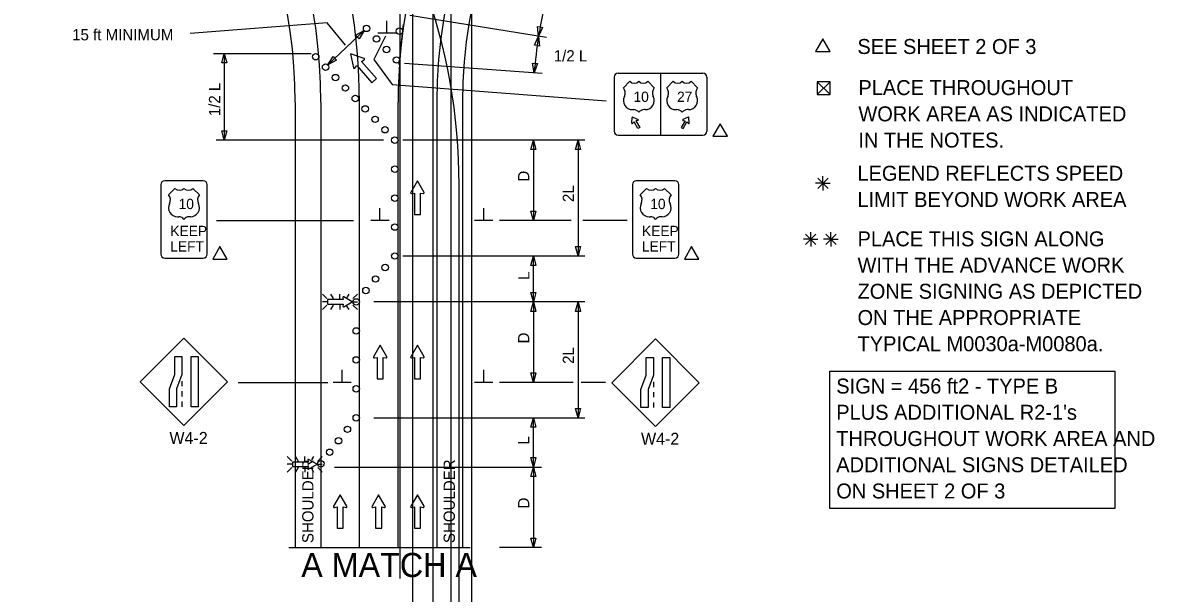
# Model space of a CAD drawing. Extents: x 16554 to 19508, y 5694 to 7079.
# Drawn here: x 16738 to 17442, y 6130 to 6485 of the extents above; entities that cross this region are included whole.
import ezdxf

# ---------------------------------------------------------------- set-up
doc = ezdxf.new("R2010")
doc.units = 0
for name, color, linetype in [('ALI_LEGAL_EX', 7, 'Continuous'), ('MT_SCRATCH_LEVEL_E', 7, 'Continuous'), ('PAVT_EDGE_EX', 7, 'Continuous'), ('TRAFFIC_SIGNS_PR', 7, 'Continuous'), ('TYPICAL_EX', 7, 'Continuous'), ('TYPICAL_TEXT_DIMEN_EX', 7, 'Continuous'), ('TYPICAL_TEXT_DIMEN_PR', 7, 'Continuous')]:
    doc.layers.add(name, color=color, linetype=linetype)

msp = doc.modelspace()

# ---------------------------------------------------------------- linework, layer by layer
at = {"layer": 'ALI_LEGAL_EX'}
for p, q in [((16980.68, 6974.12), (16980.68, 6155.98)), ((17004.68, 6974.12), (17004.68, 6155.98)), ((16980.68, 6877.04), (16980.68, 6013.12)), ((17004.68, 6877.04), (17004.68, 6013.12)), ((16973.01, 6139.03), (16973.01, 6639.38)), ((16993.65, 6024.8), (16993.65, 6525.15)), ((17017.65, 6024.8), (17017.65, 6525.15)), ((16947.82, 6158.38), (16947.82, 6435.06)), ((16971.82, 6158.38), (16971.82, 6435.06)), ((17009.75, 5773.57), (17009.75, 6383.76))]:
    msp.add_line(p, q, dxfattribs=at)
for points in [[(16972.59, 6458.6), (16975.21, 6483.46)], [(16947.82, 6358.38), (16947.82, 6383.38)], [(16971.82, 6358.38), (16971.82, 6383.38)], [(16947.82, 6258.38), (16947.82, 6283.38)], [(16971.82, 6258.38), (16971.82, 6283.38)], [(16947.82, 6158.38), (16947.82, 6183.38)], [(16971.82, 6158.38), (16971.82, 6183.38)]]:
    msp.add_lwpolyline(points, dxfattribs=at)
for centre, radius, start, end in [((16583.82, 6435.06), 364, 0, 40.19088), ((17311.82, 6435.06), 340, 137.51599, 180), ((16645.75, 6383.76), 364, 0, 40.19088)]:
    msp.add_arc(centre, radius, start, end, dxfattribs=at)
at = {"layer": 'MT_SCRATCH_LEVEL_E'}
for p, q in [((16983.79, 6386.25), (16979.68, 6379.01)), ((16987.94, 6379.01), (16983.79, 6386.25)), ((16980.16, 6378.32), (16981.94, 6378.64)), ((16981.94, 6378.64), (16981.94, 6365.38)), ((16985.68, 6365.38), (16985.68, 6378.64)), ((16985.68, 6378.64), (16987.46, 6378.32)), ((16981.94, 6365.38), (16985.68, 6365.38)), ((16960.72, 6284.09), (16956.61, 6276.85)), ((16964.86, 6276.85), (16960.72, 6284.09)), ((16983.79, 6284.09), (16979.68, 6276.85)), ((16987.94, 6276.85), (16983.79, 6284.09)), ((16957.09, 6276.17), (16958.87, 6276.48)), ((16958.87, 6276.48), (16958.87, 6263.23)), ((16962.61, 6263.23), (16962.61, 6276.48)), ((16962.61, 6276.48), (16964.39, 6276.17)), ((16980.16, 6276.17), (16981.94, 6276.48)), ((16981.94, 6276.48), (16981.94, 6263.23)), ((16985.68, 6263.23), (16985.68, 6276.48)), ((16985.68, 6276.48), (16987.46, 6276.17)), ((16958.87, 6263.23), (16962.61, 6263.23)), ((16981.94, 6263.23), (16985.68, 6263.23)), ((16935.83, 6191.19), (16931.72, 6183.95)), ((16939.98, 6183.95), (16935.83, 6191.19)), ((16959.74, 6191.19), (16955.62, 6183.95)), ((16963.88, 6183.95), (16959.74, 6191.19)), ((16983.79, 6191.19), (16979.68, 6183.95)), ((16987.94, 6183.95), (16983.79, 6191.19)), ((16932.2, 6183.27), (16933.98, 6183.58)), ((16933.98, 6183.58), (16933.98, 6170.32)), ((16937.72, 6170.32), (16937.72, 6183.58)), ((16937.72, 6183.58), (16939.5, 6183.27)), ((16956.11, 6183.27), (16957.88, 6183.58)), ((16957.88, 6183.58), (16957.88, 6170.32)), ((16961.63, 6170.32), (16961.63, 6183.58)), ((16961.63, 6183.58), (16963.4, 6183.27)), ((16980.16, 6183.27), (16981.94, 6183.58)), ((16981.94, 6183.58), (16981.94, 6170.32)), ((16985.68, 6170.32), (16985.68, 6183.58)), ((16985.68, 6183.58), (16987.46, 6183.27)), ((16933.98, 6170.32), (16937.72, 6170.32)), ((16957.88, 6170.32), (16961.63, 6170.32)), ((16981.94, 6170.32), (16985.68, 6170.32))]:
    msp.add_line(p, q, dxfattribs=at)
for centre, start, end in [((16980.09, 6378.78), 150.42484, 279.96381), ((16987.53, 6378.78), 260.03619, 29.77312), ((16957.01, 6276.63), 150.42484, 279.96381), ((16964.46, 6276.63), 260.03619, 29.77312), ((16980.09, 6276.63), 150.42484, 279.96381), ((16987.53, 6276.63), 260.03619, 29.77312), ((16932.13, 6183.72), 150.42484, 279.96381), ((16939.57, 6183.73), 260.03619, 29.77312), ((16956.03, 6183.72), 150.42484, 279.96381), ((16963.47, 6183.73), 260.03619, 29.77312), ((16980.09, 6183.72), 150.42484, 279.96381), ((16987.53, 6183.73), 260.03619, 29.77312)]:
    msp.add_arc(centre, 0.463, start, end, dxfattribs=at)
at = {"layer": 'PAVT_EDGE_EX'}
for p, q in [((16907.82, 6435.06), (16907.82, 6158.38)), ((16923.82, 6435.06), (16923.82, 6158.38)), ((16995.82, 6435.06), (16995.82, 6158.38)), ((17011.82, 6435.06), (17011.82, 6158.38))]:
    msp.add_line(p, q, dxfattribs=at)
for centre, radius, start, end in [((17311.82, 6435.06), 316, 105.2177, 180), ((16583.82, 6435.06), 340, 0, 61.48623), ((17311.82, 6435.06), 300, 105.2177, 180), ((16583.82, 6435.06), 324, 0, 61.48623), ((17311.82, 6435.06), 300, 180, 180.00000277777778)]:
    msp.add_arc(centre, radius, start, end, dxfattribs=at)
at = {"layer": 'TRAFFIC_SIGNS_PR'}
for p, q in [((17106.11, 6450.65), (17106.11, 6417.05)), ((17108.51, 6453.05), (17161.31, 6453.05)), ((17134.91, 6453.05), (17134.91, 6414.65)), ((17163.71, 6450.65), (17163.71, 6417.05)), ((17117.09, 6422), (17117.37, 6425.62)), ((17117.74, 6425.84), (17121.02, 6424.27)), ((17152.07, 6425.84), (17148.8, 6424.27)), ((17152.73, 6422), (17152.44, 6425.62)), ((17108.51, 6414.65), (17161.31, 6414.65)), ((16824.36, 6383.86), (16824.36, 6340.66)), ((16850.76, 6386.26), (16826.76, 6386.26)), ((16853.16, 6340.66), (16853.16, 6383.86)), ((17117.49, 6383.86), (17117.49, 6340.66)), ((17143.88, 6386.26), (17119.88, 6386.26)), ((17146.28, 6340.66), (17146.28, 6383.86)), ((16826.76, 6338.26), (16850.76, 6338.26)), ((17119.88, 6338.26), (17143.88, 6338.26)), ((16927.59, 6313.05), (16924.77, 6315.87)), ((16927.59, 6311.02), (16924.77, 6311.02)), ((16929.89, 6315.87), (16931.52, 6313.05)), ((16935.68, 6313.05), (16935.68, 6315.87)), ((16941.15, 6315.87), (16939.94, 6313.77)), ((16946.58, 6315.86), (16943.76, 6313.05)), ((16943.76, 6311.02), (16946.58, 6311.02)), ((16927.59, 6308.98), (16924.77, 6306.16)), ((16931.54, 6308.98), (16929.91, 6306.16)), ((16935.68, 6308.98), (16935.68, 6306.16)), ((16939.86, 6308.35), (16941.12, 6306.16)), ((16946.58, 6306.16), (16943.76, 6308.98)), ((16838.75, 6288.47), (16811.6, 6261.32)), ((16865.9, 6261.32), (16838.75, 6288.47)), ((17131.83, 6287.95), (17104.68, 6260.79)), ((17158.99, 6260.79), (17131.83, 6287.95)), ((16811.6, 6261.32), (16838.75, 6234.17)), ((16837.5, 6261.81), (16837.5, 6258.61)), ((16838.75, 6234.17), (16865.9, 6261.32)), ((17104.68, 6260.79), (17131.83, 6233.64)), ((17130.59, 6261.28), (17130.59, 6258.08)), ((17131.83, 6233.64), (17158.99, 6260.79)), ((16837.5, 6255.41), (16837.5, 6252.21)), ((17130.59, 6254.88), (17130.59, 6251.68)), ((16837.5, 6249.01), (16837.5, 6245.81)), ((17130.59, 6248.48), (17130.59, 6245.28)), ((16905.72, 6212.1), (16902.9, 6214.92)), ((16908.01, 6214.91), (16909.64, 6212.1)), ((16913.8, 6212.1), (16913.8, 6214.91)), ((16919.27, 6214.91), (16918.06, 6212.82)), ((16924.71, 6214.91), (16921.89, 6212.1)), ((16905.72, 6210.06), (16902.9, 6210.06)), ((16905.72, 6208.03), (16902.9, 6205.21)), ((16909.67, 6208.03), (16908.04, 6205.21)), ((16913.8, 6208.03), (16913.8, 6205.21)), ((16917.99, 6207.4), (16919.25, 6205.21)), ((16921.89, 6210.06), (16924.71, 6210.06)), ((16924.71, 6205.21), (16921.89, 6208.03))]:
    msp.add_line(p, q, dxfattribs=at)
for points in [[(17120.98, 6423.79), (17119.57, 6423.4), (17122.08, 6419.42), (17120.76, 6418.65), (17118.57, 6422.82), (17117.53, 6421.79)], [(17148.83, 6423.79), (17150.24, 6423.4), (17147.73, 6419.42), (17149.06, 6418.65), (17151.25, 6422.82), (17152.29, 6421.79)], [(16937.5, 6313.7), (16937.73, 6312.4), (16928.01, 6312.4), (16928.01, 6309.66), (16937.73, 6309.66), (16937.5, 6308.35)], [(16938, 6308), (16943.31, 6311.02), (16938, 6314.06)], [(16915.63, 6212.74), (16915.86, 6211.45), (16906.14, 6211.45), (16906.14, 6208.7), (16915.86, 6208.7), (16915.63, 6207.4)], [(16916.13, 6207.05), (16921.44, 6210.06), (16916.13, 6213.1)]]:
    msp.add_lwpolyline(points, dxfattribs=at)
for points in [[(16837.5, 6277.06), (16837.5, 6265.88), (16834.16, 6256.99), (16834.16, 6245.81), (16829.66, 6245.81), (16829.66, 6256.99), (16833.01, 6265.88), (16833.01, 6277.06)], [(16847.64, 6277.06), (16847.64, 6245.81), (16843.14, 6245.81), (16843.14, 6277.06)], [(17130.59, 6276.53), (17130.59, 6265.35), (17127.24, 6256.47), (17127.24, 6245.28), (17122.75, 6245.28), (17122.75, 6256.47), (17126.09, 6265.35), (17126.09, 6276.53)], [(17140.72, 6276.53), (17140.72, 6245.28), (17136.23, 6245.28), (17136.23, 6276.53)]]:
    msp.add_lwpolyline(points, close=True, dxfattribs=at)
for centre in [(16952.24, 6480.91), (16972.68, 6479.22), (16958.43, 6474.38), (16920.63, 6463.35), (16964.62, 6467.85), (16926.78, 6456.87), (16970.82, 6461.32), (16932.93, 6450.38), (16939.07, 6443.89), (16945.22, 6437.4), (16951.37, 6430.92), (16957.52, 6424.43), (16963.67, 6417.94), (16969.82, 6411.46), (16969.82, 6411.46), (16969.82, 6393.46), (16969.82, 6375.46), (16969.82, 6357.46), (16969.82, 6339.51), (16963.82, 6332.37), (16957.82, 6325.23), (16951.82, 6318.09), (16945.82, 6310.95), (16945.82, 6292.94), (16945.82, 6274.94), (16945.82, 6256.94), (16945.82, 6238.94), (16940.32, 6231.81), (16934.82, 6224.69), (16929.32, 6217.56), (16923.83, 6210.43)]:
    msp.add_circle(centre, 2, dxfattribs=at)
for centre, radius, start, end in [((17108.51, 6450.65), 2.4, 90, 180), ((17108.51, 6450.65), 2.4, 90, 180), ((17161.31, 6450.65), 2.4, 0, 90), ((17117.35, 6421.98), 0.26, 175.51775, 314.01151), ((17117.63, 6425.6), 0.26, 64.48226, 175.51774), ((17120.91, 6424.04), 0.26, 285.9885, 64.48226), ((17148.91, 6424.04), 0.26, 115.51774, 254.0115), ((17152.19, 6425.6), 0.26, 4.48226, 115.51774), ((17152.47, 6421.98), 0.26, 225.98849, 4.48225), ((17108.51, 6417.05), 2.4, 180, 270), ((17161.31, 6417.05), 2.4, 270, 0), ((16826.76, 6383.86), 2.4, 90, 180), ((16850.76, 6383.86), 2.4, 0, 90), ((17119.88, 6383.86), 2.4, 90, 180), ((17143.88, 6383.86), 2.4, 0, 90), ((16826.76, 6340.66), 2.4, 180, 270), ((16850.76, 6340.66), 2.4, 270, 0), ((17119.88, 6340.66), 2.4, 180, 270), ((17143.88, 6340.66), 2.4, 270, 0), ((16937.84, 6313.76), 0.341, 61.48329, 189.95933), ((16937.84, 6308.3), 0.341, 170.73078, 298.89165), ((16915.97, 6212.8), 0.341, 61.48329, 189.95933), ((16915.97, 6207.35), 0.341, 170.73078, 298.89165)]:
    msp.add_arc(centre, radius, start, end, dxfattribs=at)
at = {"layer": 'TYPICAL_EX'}
for p, q in [((17111.86, 6444.05), (17115.86, 6448.05)), ((17131.06, 6444.05), (17127.06, 6448.05)), ((17138.76, 6444.05), (17142.76, 6448.05)), ((17157.96, 6444.05), (17153.96, 6448.05)), ((17117.45, 6430.44), (17118.25, 6430.44)), ((17125.46, 6430.44), (17124.66, 6430.44)), ((17144.35, 6430.44), (17145.15, 6430.44)), ((17152.36, 6430.44), (17151.56, 6430.44)), ((16829.16, 6377.46), (16833.16, 6381.46)), ((16848.36, 6377.46), (16844.36, 6381.46)), ((17122.28, 6377.46), (17126.28, 6381.46)), ((17141.49, 6377.46), (17137.49, 6381.46)), ((16834.75, 6363.85), (16835.55, 6363.85)), ((16842.76, 6363.85), (16841.96, 6363.85)), ((17127.88, 6363.85), (17128.68, 6363.85)), ((17135.89, 6363.85), (17135.09, 6363.85))]:
    msp.add_line(p, q, dxfattribs=at)
for centre, radius, start, end in [((17108.07, 6440.85), 4.96, 333.09768, 40.19361), ((17118.66, 6450.96), 4.04, 226.14041, 313.85958), ((17124.26, 6450.96), 4.04, 226.14042, 313.85959), ((17134.85, 6440.85), 4.96, 139.80639, 206.90233), ((17134.97, 6440.85), 4.96, 333.09768, 40.19361), ((17145.56, 6450.96), 4.04, 226.14041, 313.85958), ((17151.16, 6450.96), 4.04, 226.14042, 313.85959), ((17161.75, 6440.85), 4.96, 139.80639, 206.90233), ((17117.46, 6436.03), 5.59, 152.6698, 269.90132), ((17125.45, 6436.03), 5.59, 270.09868, 27.3302), ((17144.36, 6436.03), 5.59, 152.6698, 269.90132), ((17152.35, 6436.03), 5.59, 270.09868, 27.3302), ((17118.26, 6426.43), 4.01, 37.1038, 90.13853), ((17124.65, 6426.43), 4.01, 89.86147, 142.8962), ((17145.16, 6426.43), 4.01, 37.1038, 90.13853), ((17151.55, 6426.43), 4.01, 89.86147, 142.8962), ((16835.96, 6384.37), 4.04, 226.14041, 313.85958), ((16841.56, 6384.37), 4.04, 226.14042, 313.85959), ((17129.09, 6384.37), 4.04, 226.14041, 313.85958), ((17134.69, 6384.37), 4.04, 226.14042, 313.85959), ((16825.37, 6374.26), 4.96, 333.09768, 40.19361), ((16852.15, 6374.26), 4.96, 139.80639, 206.90233), ((17118.49, 6374.26), 4.96, 333.09768, 40.19361), ((17145.28, 6374.26), 4.96, 139.80639, 206.90233), ((16834.76, 6369.44), 5.59, 152.6698, 269.90132), ((16842.75, 6369.44), 5.59, 270.09868, 27.3302), ((17127.89, 6369.44), 5.59, 152.6698, 269.90132), ((17135.88, 6369.44), 5.59, 270.09868, 27.3302), ((16835.56, 6359.84), 4.01, 37.1038, 90.13853), ((16841.95, 6359.84), 4.01, 89.86147, 142.8962), ((17128.69, 6359.84), 4.01, 37.1038, 90.13853), ((17135.08, 6359.84), 4.01, 89.86147, 142.8962)]:
    msp.add_arc(centre, radius, start, end, dxfattribs=at)
at = {"layer": 'TYPICAL_TEXT_DIMEN_EX'}
msp.add_lwpolyline([(17240.08, 6267.86), (17417.36, 6267.86), (17417.36, 6182.54), (17240.08, 6182.54)], close=True, dxfattribs=at)
at = {"layer": 'TYPICAL_TEXT_DIMEN_PR'}
for p, q in [((16964.92, 6477.95), (16964.92, 6485.73)), ((17064.05, 6475.22), (16979.21, 6488.97)), ((16927.8, 6484.32), (16842.59, 6477.76)), ((16939.16, 6470.62), (16927.8, 6484.32)), ((16950.78, 6479.54), (16928.23, 6458.24)), ((16945.44, 6476.66), (16950.78, 6479.54)), ((16950.78, 6479.54), (16947.6, 6474.37)), ((16970.55, 6477.95), (16959.3, 6477.95)), ((17059.11, 6476.02), (17058.5, 6482.06)), ((17058.5, 6482.06), (17060.05, 6481.81)), ((17059.11, 6476.02), (17058.5, 6482.06)), ((17058.5, 6482.06), (17060.05, 6481.81)), ((17061.6, 6481.55), (17059.11, 6476.02)), ((17061.6, 6481.55), (17059.11, 6476.02)), ((17060.05, 6481.81), (17061.6, 6481.55)), ((17060.05, 6481.81), (17061.6, 6481.55)), ((16946.52, 6475.52), (16945.44, 6476.66)), ((16947.6, 6474.37), (16946.52, 6475.52)), ((16964.04, 6476.17), (16956.66, 6461.67)), ((17056.63, 6470.48), (17059.11, 6476.02)), ((17059.11, 6476.02), (17059.73, 6469.98)), ((16857.14, 6465.35), (16917.72, 6465.35)), ((16862.25, 6459.49), (16863.82, 6465.35)), ((16863.82, 6465.35), (16863.82, 6411.51)), ((16863.82, 6465.35), (16865.39, 6459.49)), ((16950.7, 6462.31), (16942.28, 6465.2)), ((16942.28, 6465.2), (16944.08, 6456.51)), ((17058.18, 6470.23), (17056.63, 6470.48)), ((17059.73, 6469.98), (17058.18, 6470.23)), ((16863.82, 6459.49), (16862.25, 6459.49)), ((16865.39, 6459.49), (16863.82, 6459.49)), ((16928.23, 6458.24), (16931.41, 6463.41)), ((16933.57, 6461.12), (16928.23, 6458.24)), ((16931.41, 6463.41), (16932.49, 6462.26)), ((16932.49, 6462.26), (16933.57, 6461.12)), ((16944.95, 6456.3), (16946.15, 6457.8)), ((16946.15, 6457.8), (16955.47, 6447.16)), ((16949.15, 6460.43), (16950.8, 6461.43)), ((16958.47, 6449.8), (16949.15, 6460.43)), ((16956.66, 6461.67), (16968.23, 6446.16)), ((17061.46, 6452.97), (16975.72, 6459.1)), ((17056.47, 6453.32), (17055.32, 6459.28)), ((17055.32, 6459.28), (17056.89, 6459.17)), ((17058.45, 6459.06), (17056.47, 6453.32)), ((17056.89, 6459.17), (17058.45, 6459.06)), ((16955.47, 6447.16), (16958.47, 6449.8)), ((16968.23, 6446.16), (17101.17, 6435.93)), ((17232.27, 6447.79), (17240.27, 6439.79)), ((17232.27, 6439.79), (17240.27, 6447.79)), ((16863.82, 6411.51), (16862.25, 6417.37)), ((16862.25, 6417.37), (16863.82, 6417.37)), ((16863.82, 6417.37), (16865.39, 6417.37)), ((16865.39, 6417.37), (16863.82, 6411.51)), ((16962.71, 6411.51), (16858.82, 6411.51)), ((17087.96, 6411.51), (16974.86, 6411.51)), ((17054.34, 6405.65), (17055.91, 6411.51)), ((17055.91, 6411.51), (17057.48, 6405.65)), ((17055.91, 6411.51), (17055.91, 6361.51)), ((17082.15, 6405.65), (17083.72, 6411.51)), ((17083.72, 6411.51), (17083.72, 6339.51)), ((17083.72, 6411.51), (17085.29, 6405.65)), ((17055.91, 6405.65), (17054.34, 6405.65)), ((17057.48, 6405.65), (17055.91, 6405.65)), ((17083.72, 6405.65), (17082.15, 6405.65)), ((17085.29, 6405.65), (17083.72, 6405.65)), ((17232.64, 6387.92), (17239.02, 6381.54)), ((17239.02, 6387.92), (17232.64, 6381.54)), ((17235.83, 6384.73), (17235.83, 6389.18)), ((17235.83, 6384.73), (17231.3, 6384.73)), ((17235.83, 6384.73), (17239.02, 6384.73)), ((17235.83, 6384.73), (17240.31, 6384.73)), ((17235.83, 6384.73), (17235.83, 6380.23)), ((16960.57, 6361.51), (16960.57, 6369.29)), ((17025.04, 6361.51), (17025.04, 6369.29)), ((17055.91, 6361.51), (17054.34, 6367.37)), ((17054.34, 6367.37), (17055.91, 6367.37)), ((17055.91, 6367.37), (17057.48, 6367.37)), ((17057.48, 6367.37), (17055.91, 6361.51)), ((16858.91, 6361.51), (16944.03, 6361.51)), ((16966.19, 6361.51), (16954.94, 6361.51)), ((17030.66, 6361.51), (17019.41, 6361.51)), ((17079.49, 6361.51), (17034.91, 6361.51)), ((17114.15, 6361.51), (17086.72, 6361.51)), ((17225.05, 6353.13), (17231.42, 6346.75)), ((17231.42, 6353.13), (17225.05, 6346.75)), ((17228.24, 6349.94), (17228.24, 6354.4)), ((17237.6, 6353.13), (17243.98, 6346.75)), ((17243.98, 6353.13), (17237.6, 6346.75)), ((17240.79, 6349.94), (17240.79, 6354.4)), ((17083.72, 6339.51), (17082.15, 6345.37)), ((17082.15, 6345.37), (17083.72, 6345.37)), ((17083.72, 6345.37), (17085.29, 6345.37)), ((17085.29, 6345.37), (17083.72, 6339.51)), ((17228.24, 6349.94), (17223.7, 6349.94)), ((17228.24, 6349.94), (17231.42, 6349.94)), ((17228.24, 6349.94), (17232.71, 6349.94)), ((17228.24, 6349.94), (17228.24, 6345.44)), ((17240.79, 6349.94), (17236.26, 6349.94)), ((17240.79, 6349.94), (17243.98, 6349.94)), ((17240.79, 6349.94), (17245.27, 6349.94)), ((17240.79, 6349.94), (17240.79, 6345.44)), ((16974.86, 6339.51), (17087.96, 6339.51)), ((17054.34, 6333.65), (17055.91, 6339.51)), ((17055.91, 6310.94), (17055.91, 6339.51)), ((17055.91, 6339.51), (17057.48, 6333.65)), ((17055.91, 6333.65), (17054.34, 6333.65)), ((17057.48, 6333.65), (17055.91, 6333.65)), ((17055.91, 6310.94), (17054.34, 6316.81)), ((17054.34, 6316.81), (17055.91, 6316.81)), ((17055.91, 6316.81), (17057.48, 6316.81)), ((17057.48, 6316.81), (17055.91, 6310.94)), ((17087.96, 6310.94), (16956.81, 6310.94)), ((17054.34, 6305.08), (17055.91, 6310.94)), ((17055.91, 6310.94), (17055.91, 6260.94)), ((17055.91, 6310.94), (17057.48, 6305.08)), ((17082.15, 6305.08), (17083.72, 6310.94)), ((17083.72, 6310.94), (17085.29, 6305.08)), ((17083.72, 6310.94), (17083.72, 6238.94)), ((17055.91, 6305.08), (17054.34, 6305.08)), ((17057.48, 6305.08), (17055.91, 6305.08)), ((17083.72, 6305.08), (17082.15, 6305.08)), ((17085.29, 6305.08), (17083.72, 6305.08)), ((16937.1, 6260.94), (16937.1, 6268.73)), ((17025.04, 6260.94), (17025.04, 6268.73)), ((16872.52, 6260.94), (16928.11, 6260.94)), ((16942.73, 6260.94), (16931.48, 6260.94)), ((17030.66, 6260.94), (17019.41, 6260.94)), ((17080.65, 6260.94), (17034.91, 6260.94)), ((17055.91, 6260.94), (17054.34, 6266.81)), ((17054.34, 6266.81), (17055.91, 6266.81)), ((17055.91, 6266.81), (17057.48, 6266.81)), ((17057.48, 6266.81), (17055.91, 6260.94)), ((17100.8, 6260.94), (17085.61, 6260.94)), ((16956.81, 6238.94), (17087.96, 6238.94)), ((17054.34, 6233.08), (17055.91, 6238.94)), ((17055.91, 6208.38), (17055.91, 6238.94)), ((17055.91, 6238.94), (17057.48, 6233.08)), ((17083.72, 6238.94), (17082.15, 6244.81)), ((17082.15, 6244.81), (17083.72, 6244.81)), ((17083.72, 6244.81), (17085.29, 6244.81)), ((17085.29, 6244.81), (17083.72, 6238.94)), ((17055.91, 6233.08), (17054.34, 6233.08)), ((17057.48, 6233.08), (17055.91, 6233.08)), ((17055.91, 6208.38), (17054.34, 6214.24)), ((17054.34, 6214.24), (17055.91, 6214.24)), ((17055.91, 6214.24), (17057.48, 6214.24)), ((17057.48, 6214.24), (17055.91, 6208.38)), ((16932.31, 6208.38), (17060.91, 6208.38)), ((16933.08, 6208.38), (17060.91, 6208.38)), ((17054.34, 6202.52), (17055.91, 6208.38)), ((17055.91, 6208.38), (17055.91, 6158.38)), ((17055.91, 6208.38), (17057.48, 6202.52)), ((17055.91, 6202.52), (17054.34, 6202.52)), ((17057.48, 6202.52), (17055.91, 6202.52)), ((17055.91, 6158.38), (17054.34, 6164.24)), ((17054.34, 6164.24), (17055.91, 6164.24)), ((17055.91, 6164.24), (17057.48, 6164.24)), ((17057.48, 6164.24), (17055.91, 6158.38)), ((16903.89, 6158.38), (17016.54, 6158.38)), ((17060.91, 6158.38), (17034.91, 6158.38))]:
    msp.add_line(p, q, dxfattribs=at)
for points in [[(17235.74, 6474.5), (17231.22, 6466.67), (17240.27, 6466.67)], [(17232.27, 6447.79), (17232.27, 6439.79), (17240.27, 6439.79), (17240.27, 6447.79)], [(17171.94, 6421.72), (17167.42, 6413.89), (17176.47, 6413.89)], [(16861.12, 6345.44), (16856.6, 6337.6), (16865.65, 6337.6)], [(17154.26, 6345.44), (17149.73, 6337.6), (17158.78, 6337.6)]]:
    msp.add_lwpolyline(points, close=True, dxfattribs=at)
for centre, radius, start, end in [((17311.82, 6435.06), 256, 167.0592, 170.79286), ((17311.82, 6435.06), 256, 170.79286, 175.90841), ((16950.53, 6461.84), 0.494, 301.27371, 71.01063), ((16944.56, 6456.61), 0.494, 191.66235, 321.20132)]:
    msp.add_arc(centre, radius, start, end, dxfattribs=at)

# ---------------------------------------------------------------- texts
at = {"layer": 'TRAFFIC_SIGNS_PR'}
for s, height, p in [('10', 6.4, (17118.12, 6435.25)), ('27', 6.4, (17145.19, 6435.25)), ('10', 6.4, (16835.42, 6368.66)), ('10', 6.4, (17128.54, 6368.66)), ('KEEP', 6.4, (16830.29, 6351.86)), ('KEEP', 6.4, (17123.42, 6351.86)), ('LEFT', 6.4, (16830.21, 6342.26)), ('LEFT', 6.4, (17123.33, 6342.26)), ('W4-2', 7.44, (16829.71, 6222.73)), ('W4-2', 7.44, (17122.79, 6222.2))]:
    msp.add_text(s, height=height, dxfattribs=at).set_placement(p)
at = {"layer": 'TYPICAL_TEXT_DIMEN_EX'}
for s, p in [('SEE SHEET 2 OF 3', (17257.28, 6465.04)), ('PLACE THROUGHOUT', (17257.89, 6439.49)), ('WORK AREA AS INDICATED', (17257.89, 6423.19)), ('IN THE NOTES.', (17257.89, 6406.89)), ('LEGEND REFLECTS SPEED', (17257.28, 6386.26)), ('LIMIT BEYOND WORK AREA', (17257.28, 6369.96)), ('PLACE THIS SIGN ALONG', (17257.37, 6345.52)), ('WITH THE ADVANCE WORK', (17257.37, 6329.22)), ('ZONE SIGNING AS DEPICTED', (17257.37, 6312.92)), ('ON THE APPROPRIATE', (17257.37, 6296.62)), ('TYPICAL M0030a-M0080a.', (17257.37, 6280.32)), ('SIGN = 456 ft2 - TYPE B', (17244.14, 6254.03)), ("PLUS ADDITIONAL R2-1's", (17244.14, 6237.73)), ('THROUGHOUT WORK AREA AND', (17244.14, 6221.43)), ('ADDITIONAL SIGNS DETAILED', (17244.14, 6205.13)), ('ON SHEET 2 OF 3', (17244.14, 6188.83))]:
    msp.add_text(s, height=9.3, dxfattribs=at).set_placement(p)
at = {"layer": 'TYPICAL_TEXT_DIMEN_PR'}
for s, height, p in [('15 ft MINIMUM', 7, (16769.25, 6473.51)), ('1/2 L', 7, (17068.56, 6460.4)), ('A MATCH A', 15, (16911.63, 6139.98))]:
    msp.add_text(s, height=height, dxfattribs=at).set_placement(p)
for s, p in [('1/2 L', (16861.26, 6426.37)), ('D', (17053.35, 6385.73)), ('2L', (17081.16, 6373.01)), ('L', (17053.45, 6324.58)), ('D', (17053.35, 6285.16)), ('2L', (17081.16, 6272.45)), ('L', (17053.35, 6222.24)), ('SHOULDER', (16919.25, 6161.09)), ('SHOULDER', (17007.11, 6161.09)), ('D', (17053.35, 6182.6))]:
    msp.add_text(s, height=7, rotation=90, dxfattribs=at).set_placement(p)

doc.saveas('drawing.dxf')
